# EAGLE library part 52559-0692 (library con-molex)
FFC/FPC-to-Board 0.50mm (.020") SMT, Vertical, ZIF Receptacle Source: http://www.molex.com/product/ffc/52559.html
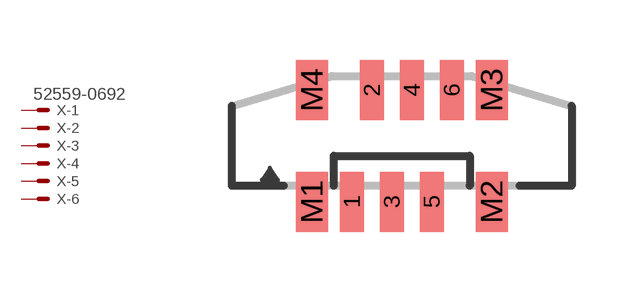
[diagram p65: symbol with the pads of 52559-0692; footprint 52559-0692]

Designator prefix X; gates -1=MV -2=M -3=M -4=M -5=M -6=M

## 52559-0692 (MPN: 52559-0692; OC_FARNELL: unknown; OC_NEWARK: 92M6167)  [52559-0692]
1  -1:S  pas
2  -2:S  pas
3  -3:S  pas
4  -4:S  pas
5  -5:S  pas
6  -6:S  pas

## Footprint 52559-0692 (pad centres in mm)
FFC/FPC-to-Board 0.50mm (.020") SMT, Vertical, ZIF Receptacle Source: http://www.molex.com/product/ffc/52559.html
smd 0.6 x 1.5: 1 -1.25,-1.4; 2 -0.75,1.4; 3 -0.25,-1.4; 4 0.25,1.4; 5 0.75,-1.4; 6 1.25,1.4
smd 0.8 x 1.5: M1 -2.25,-1.4; M2 2.25,-1.4; M3 2.25,1.4; M4 -2.25,1.4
